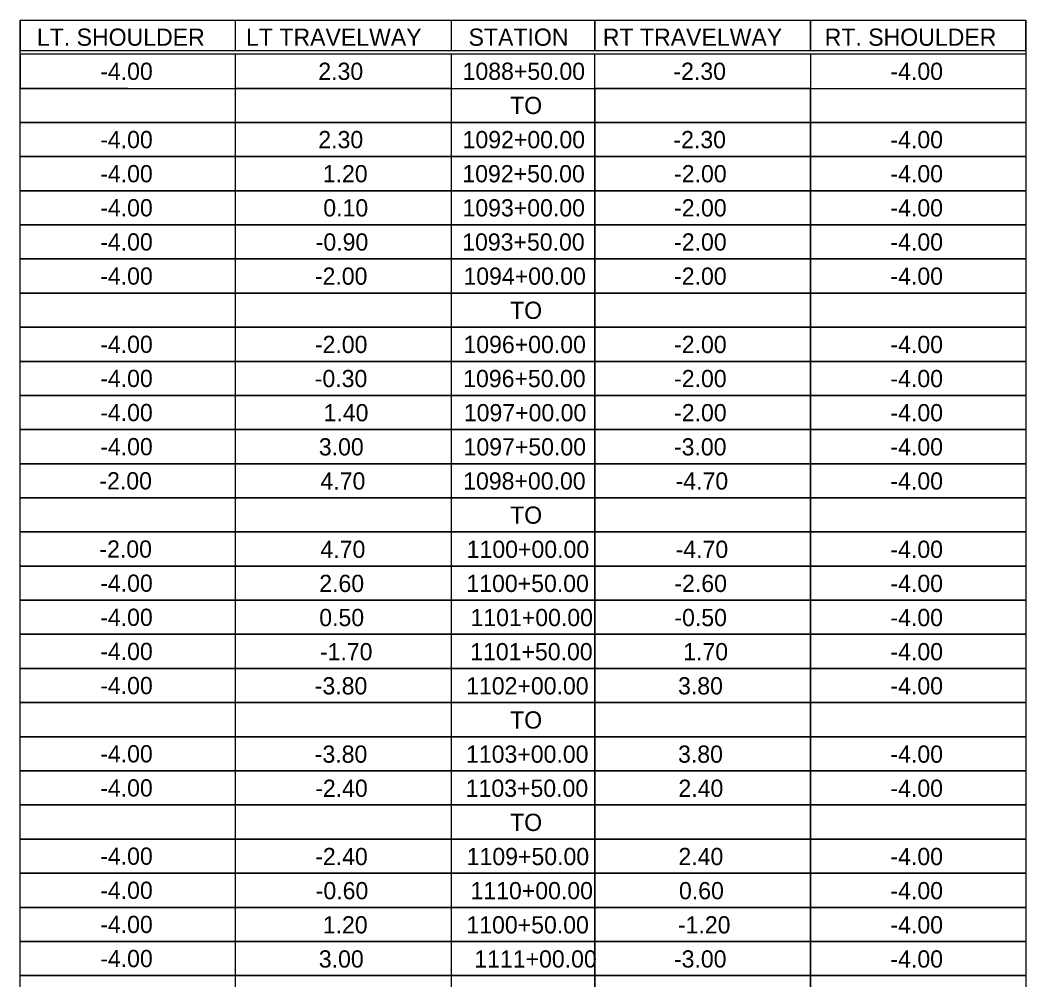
# Model space of a CAD drawing. Extents: x 1026502 to 1027102, y 781811 to 782040.
# Drawn here: x 1027074.42 to 1027102.42, y 781893.51 to 781920.24 of the extents above; entities that cross this region are included whole.
import ezdxf

# ---------------------------------------------------------------- set-up
doc = ezdxf.new("R2010")
doc.units = 0
for name, color, linetype in [('ANNOTATION', 7, 'Continuous'), ('BORDER', 7, 'Continuous'), ('DIMENSIONS', 7, 'Continuous')]:
    doc.layers.add(name, color=color, linetype=linetype)

msp = doc.modelspace()

# ---------------------------------------------------------------- linework, layer by layer
at = {"layer": 'ANNOTATION'}
msp.add_lwpolyline([(1027074.415, 781920.244), (1027102.415, 781920.244), (1027102.415, 781866.071), (1027074.415, 781866.071)], close=True, dxfattribs=at)
at = {"layer": 'BORDER'}
for p, q in [((1027074.415, 781920.244), (1027074.415, 781919.399)), ((1027077.415, 781919.293), (1027074.415, 781919.293)), ((1027074.415, 781919.293), (1027074.415, 781918.343)), ((1027102.415, 781919.293), (1027102.415, 781918.343)), ((1027077.415, 781918.343), (1027074.415, 781918.343)), ((1027077.415, 781918.343), (1027074.415, 781918.343)), ((1027077.415, 781917.393), (1027074.415, 781917.393)), ((1027077.415, 781917.393), (1027074.415, 781917.393)), ((1027077.415, 781917.393), (1027080.415, 781917.393)), ((1027077.415, 781916.442), (1027074.415, 781916.442)), ((1027077.415, 781916.442), (1027074.415, 781916.442)), ((1027077.415, 781916.442), (1027080.415, 781916.442)), ((1027077.415, 781915.492), (1027074.415, 781915.492)), ((1027077.415, 781915.492), (1027074.415, 781915.492)), ((1027077.415, 781915.492), (1027080.415, 781915.492)), ((1027077.415, 781914.541), (1027074.415, 781914.541)), ((1027077.415, 781914.541), (1027074.415, 781914.541)), ((1027077.415, 781914.541), (1027080.415, 781914.541)), ((1027077.415, 781913.591), (1027074.415, 781913.591)), ((1027077.415, 781913.591), (1027074.415, 781913.591)), ((1027077.415, 781913.591), (1027080.415, 781913.591)), ((1027077.415, 781912.641), (1027074.415, 781912.641)), ((1027077.415, 781912.641), (1027074.415, 781912.641)), ((1027077.415, 781912.641), (1027080.415, 781912.641)), ((1027077.415, 781911.69), (1027074.415, 781911.69)), ((1027077.415, 781911.69), (1027074.415, 781911.69)), ((1027077.415, 781911.69), (1027080.415, 781911.69)), ((1027077.415, 781910.74), (1027074.415, 781910.74)), ((1027077.415, 781910.74), (1027074.415, 781910.74)), ((1027077.415, 781910.74), (1027080.415, 781910.74)), ((1027077.415, 781909.789), (1027074.415, 781909.789)), ((1027077.415, 781909.789), (1027074.415, 781909.789)), ((1027077.415, 781909.789), (1027080.415, 781909.789)), ((1027077.415, 781908.839), (1027074.415, 781908.839)), ((1027077.415, 781908.839), (1027074.415, 781908.839)), ((1027077.415, 781908.839), (1027080.415, 781908.839)), ((1027077.415, 781907.889), (1027074.415, 781907.889)), ((1027077.415, 781907.889), (1027074.415, 781907.889)), ((1027077.415, 781907.889), (1027080.415, 781907.889)), ((1027077.415, 781906.938), (1027074.415, 781906.938)), ((1027077.415, 781906.938), (1027074.415, 781906.938)), ((1027077.415, 781906.938), (1027080.415, 781906.938)), ((1027077.415, 781905.988), (1027074.415, 781905.988)), ((1027077.415, 781905.988), (1027074.415, 781905.988)), ((1027077.415, 781905.988), (1027080.415, 781905.988)), ((1027077.415, 781905.037), (1027074.415, 781905.037)), ((1027077.415, 781905.037), (1027074.415, 781905.037)), ((1027077.415, 781905.037), (1027080.415, 781905.037)), ((1027077.415, 781904.087), (1027074.415, 781904.087)), ((1027077.415, 781904.087), (1027074.415, 781904.087)), ((1027077.415, 781904.087), (1027080.415, 781904.087)), ((1027077.415, 781903.137), (1027074.415, 781903.137)), ((1027077.415, 781903.137), (1027074.415, 781903.137)), ((1027077.415, 781903.137), (1027080.415, 781903.137)), ((1027077.415, 781902.186), (1027074.415, 781902.186)), ((1027077.415, 781902.186), (1027074.415, 781902.186)), ((1027077.415, 781902.186), (1027080.415, 781902.186)), ((1027077.415, 781901.236), (1027074.415, 781901.236)), ((1027077.415, 781901.236), (1027074.415, 781901.236)), ((1027077.415, 781901.236), (1027080.415, 781901.236)), ((1027077.415, 781900.285), (1027074.415, 781900.285)), ((1027077.415, 781900.285), (1027074.415, 781900.285)), ((1027077.415, 781900.285), (1027080.415, 781900.285)), ((1027077.415, 781899.335), (1027074.415, 781899.335)), ((1027077.415, 781899.335), (1027074.415, 781899.335)), ((1027077.415, 781899.335), (1027080.415, 781899.335)), ((1027077.415, 781898.385), (1027074.415, 781898.385)), ((1027077.415, 781898.385), (1027074.415, 781898.385)), ((1027077.415, 781898.385), (1027080.415, 781898.385)), ((1027077.415, 781897.434), (1027074.415, 781897.434)), ((1027077.415, 781897.434), (1027074.415, 781897.434)), ((1027077.415, 781897.434), (1027080.415, 781897.434)), ((1027077.415, 781896.484), (1027074.415, 781896.484)), ((1027077.415, 781896.484), (1027074.415, 781896.484)), ((1027077.415, 781896.484), (1027080.415, 781896.484)), ((1027077.415, 781895.533), (1027074.415, 781895.533)), ((1027077.415, 781895.533), (1027074.415, 781895.533)), ((1027077.415, 781895.533), (1027080.415, 781895.533)), ((1027077.415, 781894.583), (1027074.415, 781894.583)), ((1027077.415, 781894.583), (1027074.415, 781894.583)), ((1027077.415, 781894.583), (1027080.415, 781894.583)), ((1027077.415, 781893.633), (1027074.415, 781893.633)), ((1027077.415, 781893.633), (1027074.415, 781893.633)), ((1027077.415, 781893.633), (1027080.415, 781893.633))]:
    msp.add_line(p, q, dxfattribs=at)
for points in [[(1027074.415, 781920.244), (1027102.415, 781920.244), (1027102.415, 781919.293), (1027074.415, 781919.293)], [(1027074.415, 781918.343), (1027102.415, 781918.343), (1027102.415, 781917.393), (1027074.415, 781917.393)], [(1027074.415, 781917.393), (1027102.415, 781917.393), (1027102.415, 781916.442), (1027074.415, 781916.442)], [(1027074.415, 781916.442), (1027102.415, 781916.442), (1027102.415, 781915.492), (1027074.415, 781915.492)], [(1027074.415, 781915.492), (1027102.415, 781915.492), (1027102.415, 781914.541), (1027074.415, 781914.541)], [(1027074.415, 781914.541), (1027102.415, 781914.541), (1027102.415, 781913.591), (1027074.415, 781913.591)], [(1027074.415, 781913.591), (1027102.415, 781913.591), (1027102.415, 781912.641), (1027074.415, 781912.641)], [(1027074.415, 781912.641), (1027102.415, 781912.641), (1027102.415, 781911.69), (1027074.415, 781911.69)], [(1027074.415, 781911.69), (1027102.415, 781911.69), (1027102.415, 781910.74), (1027074.415, 781910.74)], [(1027074.415, 781910.74), (1027102.415, 781910.74), (1027102.415, 781909.789), (1027074.415, 781909.789)], [(1027074.415, 781909.789), (1027102.415, 781909.789), (1027102.415, 781908.839), (1027074.415, 781908.839)], [(1027074.415, 781908.839), (1027102.415, 781908.839), (1027102.415, 781907.889), (1027074.415, 781907.889)], [(1027074.415, 781907.889), (1027102.415, 781907.889), (1027102.415, 781906.938), (1027074.415, 781906.938)], [(1027074.415, 781906.938), (1027102.415, 781906.938), (1027102.415, 781905.988), (1027074.415, 781905.988)], [(1027074.415, 781905.988), (1027102.415, 781905.988), (1027102.415, 781905.037), (1027074.415, 781905.037)], [(1027074.415, 781905.037), (1027102.415, 781905.037), (1027102.415, 781904.087), (1027074.415, 781904.087)], [(1027074.415, 781904.087), (1027102.415, 781904.087), (1027102.415, 781903.137), (1027074.415, 781903.137)], [(1027074.415, 781903.137), (1027102.415, 781903.137), (1027102.415, 781902.186), (1027074.415, 781902.186)], [(1027074.415, 781902.186), (1027102.415, 781902.186), (1027102.415, 781901.236), (1027074.415, 781901.236)], [(1027074.415, 781901.236), (1027102.415, 781901.236), (1027102.415, 781900.285), (1027074.415, 781900.285)], [(1027074.415, 781900.285), (1027102.415, 781900.285), (1027102.415, 781899.335), (1027074.415, 781899.335)], [(1027074.415, 781899.335), (1027102.415, 781899.335), (1027102.415, 781898.385), (1027074.415, 781898.385)], [(1027074.415, 781898.385), (1027102.415, 781898.385), (1027102.415, 781897.434), (1027074.415, 781897.434)], [(1027074.415, 781897.434), (1027102.415, 781897.434), (1027102.415, 781896.484), (1027074.415, 781896.484)], [(1027074.415, 781896.484), (1027102.415, 781896.484), (1027102.415, 781895.533), (1027074.415, 781895.533)], [(1027074.415, 781895.533), (1027102.415, 781895.533), (1027102.415, 781894.583), (1027074.415, 781894.583)], [(1027074.415, 781894.583), (1027102.415, 781894.583), (1027102.415, 781893.633), (1027074.415, 781893.633)], [(1027074.415, 781893.633), (1027102.415, 781893.633), (1027102.415, 781892.682), (1027074.415, 781892.682)]]:
    msp.add_lwpolyline(points, close=True, dxfattribs=at)
for points in [[(1027074.415, 781919.399), (1027102.415, 781919.399), (1027102.415, 781920.244)], [(1027080.415, 781919.399), (1027080.415, 781920.244)], [(1027086.415, 781920.244), (1027086.415, 781919.399)], [(1027090.415, 781920.244), (1027090.415, 781919.399)], [(1027090.415, 781919.399), (1027090.415, 781920.244)], [(1027096.415, 781920.244), (1027096.415, 781919.399)], [(1027096.415, 781919.399), (1027096.415, 781920.244)], [(1027102.415, 781920.244), (1027102.415, 781919.399)], [(1027086.415, 781919.293), (1027086.415, 781918.343), (1027080.415, 781918.343), (1027080.415, 781919.293)], [(1027096.415, 781919.293), (1027096.415, 781918.343), (1027090.415, 781918.343), (1027090.415, 781919.293)], [(1027086.415, 781918.343), (1027086.415, 781917.393), (1027080.415, 781917.393), (1027080.415, 781918.343)], [(1027090.415, 781918.343), (1027090.415, 781917.393), (1027086.415, 781917.393)], [(1027096.415, 781918.343), (1027096.415, 781917.393), (1027090.415, 781917.393), (1027090.415, 781918.343)], [(1027102.415, 781918.343), (1027102.415, 781917.393), (1027096.415, 781917.393), (1027096.415, 781918.343)], [(1027086.415, 781917.393), (1027086.415, 781916.442), (1027080.415, 781916.442), (1027080.415, 781917.393)], [(1027090.415, 781917.393), (1027090.415, 781916.442), (1027086.415, 781916.442)], [(1027096.415, 781917.393), (1027096.415, 781916.442), (1027090.415, 781916.442), (1027090.415, 781917.393)], [(1027102.415, 781917.393), (1027102.415, 781916.442), (1027096.415, 781916.442), (1027096.415, 781917.393)], [(1027086.415, 781916.442), (1027086.415, 781915.492), (1027080.415, 781915.492), (1027080.415, 781916.442)], [(1027090.415, 781916.442), (1027090.415, 781915.492), (1027086.415, 781915.492)], [(1027096.415, 781916.442), (1027096.415, 781915.492), (1027090.415, 781915.492), (1027090.415, 781916.442)], [(1027102.415, 781916.442), (1027102.415, 781915.492), (1027096.415, 781915.492), (1027096.415, 781916.442)], [(1027086.415, 781915.492), (1027086.415, 781914.541), (1027080.415, 781914.541), (1027080.415, 781915.492)], [(1027090.415, 781915.492), (1027090.415, 781914.541), (1027086.415, 781914.541)], [(1027096.415, 781915.492), (1027096.415, 781914.541), (1027090.415, 781914.541), (1027090.415, 781915.492)], [(1027102.415, 781915.492), (1027102.415, 781914.541), (1027096.415, 781914.541), (1027096.415, 781915.492)], [(1027086.415, 781914.541), (1027086.415, 781913.591), (1027080.415, 781913.591), (1027080.415, 781914.541)], [(1027090.415, 781914.541), (1027090.415, 781913.591), (1027086.415, 781913.591)], [(1027096.415, 781914.541), (1027096.415, 781913.591), (1027090.415, 781913.591), (1027090.415, 781914.541)], [(1027102.415, 781914.541), (1027102.415, 781913.591), (1027096.415, 781913.591), (1027096.415, 781914.541)], [(1027086.415, 781913.591), (1027086.415, 781912.641), (1027080.415, 781912.641), (1027080.415, 781913.591)], [(1027090.415, 781913.591), (1027090.415, 781912.641), (1027086.415, 781912.641)], [(1027096.415, 781913.591), (1027096.415, 781912.641), (1027090.415, 781912.641), (1027090.415, 781913.591)], [(1027102.415, 781913.591), (1027102.415, 781912.641), (1027096.415, 781912.641), (1027096.415, 781913.591)], [(1027086.415, 781912.641), (1027086.415, 781911.69), (1027080.415, 781911.69), (1027080.415, 781912.641)], [(1027090.415, 781912.641), (1027090.415, 781911.69), (1027086.415, 781911.69)], [(1027096.415, 781912.641), (1027096.415, 781911.69), (1027090.415, 781911.69), (1027090.415, 781912.641)], [(1027102.415, 781912.641), (1027102.415, 781911.69), (1027096.415, 781911.69), (1027096.415, 781912.641)], [(1027086.415, 781911.69), (1027086.415, 781910.74), (1027080.415, 781910.74), (1027080.415, 781911.69)], [(1027090.415, 781911.69), (1027090.415, 781910.74), (1027086.415, 781910.74)], [(1027096.415, 781911.69), (1027096.415, 781910.74), (1027090.415, 781910.74), (1027090.415, 781911.69)], [(1027102.415, 781911.69), (1027102.415, 781910.74), (1027096.415, 781910.74), (1027096.415, 781911.69)], [(1027086.415, 781910.74), (1027086.415, 781909.789), (1027080.415, 781909.789), (1027080.415, 781910.74)], [(1027090.415, 781910.74), (1027090.415, 781909.789), (1027086.415, 781909.789)], [(1027096.415, 781910.74), (1027096.415, 781909.789), (1027090.415, 781909.789), (1027090.415, 781910.74)], [(1027102.415, 781910.74), (1027102.415, 781909.789), (1027096.415, 781909.789), (1027096.415, 781910.74)], [(1027086.415, 781909.789), (1027086.415, 781908.839), (1027080.415, 781908.839), (1027080.415, 781909.789)], [(1027090.415, 781909.789), (1027090.415, 781908.839), (1027086.415, 781908.839)], [(1027096.415, 781909.789), (1027096.415, 781908.839), (1027090.415, 781908.839), (1027090.415, 781909.789)], [(1027102.415, 781909.789), (1027102.415, 781908.839), (1027096.415, 781908.839), (1027096.415, 781909.789)], [(1027086.415, 781908.839), (1027086.415, 781907.889), (1027080.415, 781907.889), (1027080.415, 781908.839)], [(1027090.415, 781908.839), (1027090.415, 781907.889), (1027086.415, 781907.889)], [(1027096.415, 781908.839), (1027096.415, 781907.889), (1027090.415, 781907.889), (1027090.415, 781908.839)], [(1027102.415, 781908.839), (1027102.415, 781907.889), (1027096.415, 781907.889), (1027096.415, 781908.839)], [(1027086.415, 781907.889), (1027086.415, 781906.938), (1027080.415, 781906.938), (1027080.415, 781907.889)], [(1027090.415, 781907.889), (1027090.415, 781906.938), (1027086.415, 781906.938)], [(1027096.415, 781907.889), (1027096.415, 781906.938), (1027090.415, 781906.938), (1027090.415, 781907.889)], [(1027102.415, 781907.889), (1027102.415, 781906.938), (1027096.415, 781906.938), (1027096.415, 781907.889)], [(1027086.415, 781906.938), (1027086.415, 781905.988), (1027080.415, 781905.988), (1027080.415, 781906.938)], [(1027090.415, 781906.938), (1027090.415, 781905.988), (1027086.415, 781905.988)], [(1027096.415, 781906.938), (1027096.415, 781905.988), (1027090.415, 781905.988), (1027090.415, 781906.938)], [(1027102.415, 781906.938), (1027102.415, 781905.988), (1027096.415, 781905.988), (1027096.415, 781906.938)], [(1027086.415, 781905.988), (1027086.415, 781905.037), (1027080.415, 781905.037), (1027080.415, 781905.988)], [(1027090.415, 781905.988), (1027090.415, 781905.037), (1027086.415, 781905.037)], [(1027096.415, 781905.988), (1027096.415, 781905.037), (1027090.415, 781905.037), (1027090.415, 781905.988)], [(1027102.415, 781905.988), (1027102.415, 781905.037), (1027096.415, 781905.037), (1027096.415, 781905.988)], [(1027086.415, 781905.037), (1027086.415, 781904.087), (1027080.415, 781904.087), (1027080.415, 781905.037)], [(1027090.415, 781905.037), (1027090.415, 781904.087), (1027086.415, 781904.087)], [(1027096.415, 781905.037), (1027096.415, 781904.087), (1027090.415, 781904.087), (1027090.415, 781905.037)], [(1027102.415, 781905.037), (1027102.415, 781904.087), (1027096.415, 781904.087), (1027096.415, 781905.037)], [(1027086.415, 781904.087), (1027086.415, 781903.137), (1027080.415, 781903.137), (1027080.415, 781904.087)], [(1027090.415, 781904.087), (1027090.415, 781903.137), (1027086.415, 781903.137)], [(1027096.415, 781904.087), (1027096.415, 781903.137), (1027090.415, 781903.137), (1027090.415, 781904.087)], [(1027102.415, 781904.087), (1027102.415, 781903.137), (1027096.415, 781903.137), (1027096.415, 781904.087)], [(1027086.415, 781903.137), (1027086.415, 781902.186), (1027080.415, 781902.186), (1027080.415, 781903.137)], [(1027090.415, 781903.137), (1027090.415, 781902.186), (1027086.415, 781902.186)], [(1027096.415, 781903.137), (1027096.415, 781902.186), (1027090.415, 781902.186), (1027090.415, 781903.137)], [(1027102.415, 781903.137), (1027102.415, 781902.186), (1027096.415, 781902.186), (1027096.415, 781903.137)], [(1027086.415, 781902.186), (1027086.415, 781901.236), (1027080.415, 781901.236), (1027080.415, 781902.186)], [(1027090.415, 781902.186), (1027090.415, 781901.236), (1027086.415, 781901.236)], [(1027096.415, 781902.186), (1027096.415, 781901.236), (1027090.415, 781901.236), (1027090.415, 781902.186)], [(1027102.415, 781902.186), (1027102.415, 781901.236), (1027096.415, 781901.236), (1027096.415, 781902.186)], [(1027086.415, 781901.236), (1027086.415, 781900.285), (1027080.415, 781900.285), (1027080.415, 781901.236)], [(1027090.415, 781901.236), (1027090.415, 781900.285), (1027086.415, 781900.285)], [(1027096.415, 781901.236), (1027096.415, 781900.285), (1027090.415, 781900.285), (1027090.415, 781901.236)], [(1027102.415, 781901.236), (1027102.415, 781900.285), (1027096.415, 781900.285), (1027096.415, 781901.236)], [(1027086.415, 781900.285), (1027086.415, 781899.335), (1027080.415, 781899.335), (1027080.415, 781900.285)], [(1027090.415, 781900.285), (1027090.415, 781899.335), (1027086.415, 781899.335)], [(1027096.415, 781900.285), (1027096.415, 781899.335), (1027090.415, 781899.335), (1027090.415, 781900.285)], [(1027102.415, 781900.285), (1027102.415, 781899.335), (1027096.415, 781899.335), (1027096.415, 781900.285)], [(1027086.415, 781899.335), (1027086.415, 781898.385), (1027080.415, 781898.385), (1027080.415, 781899.335)], [(1027090.415, 781899.335), (1027090.415, 781898.385), (1027086.415, 781898.385)], [(1027096.415, 781899.335), (1027096.415, 781898.385), (1027090.415, 781898.385), (1027090.415, 781899.335)], [(1027102.415, 781899.335), (1027102.415, 781898.385), (1027096.415, 781898.385), (1027096.415, 781899.335)], [(1027086.415, 781898.385), (1027086.415, 781897.434), (1027080.415, 781897.434), (1027080.415, 781898.385)], [(1027090.415, 781898.385), (1027090.415, 781897.434), (1027086.415, 781897.434)], [(1027096.415, 781898.385), (1027096.415, 781897.434), (1027090.415, 781897.434), (1027090.415, 781898.385)], [(1027102.415, 781898.385), (1027102.415, 781897.434), (1027096.415, 781897.434), (1027096.415, 781898.385)], [(1027086.415, 781897.434), (1027086.415, 781896.484), (1027080.415, 781896.484), (1027080.415, 781897.434)], [(1027090.415, 781897.434), (1027090.415, 781896.484), (1027086.415, 781896.484)], [(1027096.415, 781897.434), (1027096.415, 781896.484), (1027090.415, 781896.484), (1027090.415, 781897.434)], [(1027102.415, 781897.434), (1027102.415, 781896.484), (1027096.415, 781896.484), (1027096.415, 781897.434)], [(1027086.415, 781896.484), (1027086.415, 781895.533), (1027080.415, 781895.533), (1027080.415, 781896.484)], [(1027090.415, 781896.484), (1027090.415, 781895.533), (1027086.415, 781895.533)], [(1027096.415, 781896.484), (1027096.415, 781895.533), (1027090.415, 781895.533), (1027090.415, 781896.484)], [(1027102.415, 781896.484), (1027102.415, 781895.533), (1027096.415, 781895.533), (1027096.415, 781896.484)], [(1027086.415, 781895.533), (1027086.415, 781894.583), (1027080.415, 781894.583), (1027080.415, 781895.533)], [(1027090.415, 781895.533), (1027090.415, 781894.583), (1027086.415, 781894.583)], [(1027096.415, 781895.533), (1027096.415, 781894.583), (1027090.415, 781894.583), (1027090.415, 781895.533)], [(1027102.415, 781895.533), (1027102.415, 781894.583), (1027096.415, 781894.583), (1027096.415, 781895.533)], [(1027086.415, 781894.583), (1027086.415, 781893.633), (1027080.415, 781893.633), (1027080.415, 781894.583)], [(1027090.415, 781894.583), (1027090.415, 781893.633), (1027086.415, 781893.633)], [(1027096.415, 781894.583), (1027096.415, 781893.633), (1027090.415, 781893.633), (1027090.415, 781894.583)], [(1027102.415, 781894.583), (1027102.415, 781893.633), (1027096.415, 781893.633), (1027096.415, 781894.583)], [(1027086.415, 781893.633), (1027086.415, 781892.682), (1027080.415, 781892.682), (1027080.415, 781893.633)], [(1027090.415, 781893.633), (1027090.415, 781892.682), (1027086.415, 781892.682)], [(1027096.415, 781893.633), (1027096.415, 781892.682), (1027090.415, 781892.682), (1027090.415, 781893.633)], [(1027102.415, 781893.633), (1027102.415, 781892.682), (1027096.415, 781892.682), (1027096.415, 781893.633)]]:
    msp.add_lwpolyline(points, dxfattribs=at)

# ---------------------------------------------------------------- texts
at = {"layer": 'DIMENSIONS'}
for s, p in [('LT. SHOULDER', (1027074.883, 781919.529)), ('LT TRAVELWAY', (1027080.706, 781919.529)), ('STATION', (1027086.9, 781919.529)), ('RT TRAVELWAY', (1027090.638, 781919.529)), ('RT. SHOULDER', (1027096.814, 781919.529)), ('-4.00', (1027076.645, 781918.578)), ('2.30', (1027082.717, 781918.578)), ('1088+50.00', (1027086.734, 781918.578)), ('-2.30', (1027092.603, 781918.578)), ('-4.00', (1027098.645, 781918.578)), ('TO', (1027088.057, 781917.627)), ('-4.00', (1027076.645, 781916.677)), ('2.30', (1027082.717, 781916.676)), ('1092+00.00', (1027086.734, 781916.676)), ('-2.30', (1027092.603, 781916.676)), ('-4.00', (1027098.645, 781916.676)), ('-4.00', (1027076.645, 781915.727)), ('1.20', (1027082.841, 781915.726)), ('1092+50.00', (1027086.727, 781915.726)), ('-2.00', (1027092.622, 781915.726)), ('-4.00', (1027098.645, 781915.726)), ('-4.00', (1027076.645, 781914.777)), ('0.10', (1027082.856, 781914.775)), ('1093+00.00', (1027086.731, 781914.775)), ('-2.00', (1027092.622, 781914.775)), ('-4.00', (1027098.645, 781914.775)), ('-4.00', (1027076.645, 781913.826)), ('-0.90', (1027082.645, 781913.824)), ('1093+50.00', (1027086.723, 781913.824)), ('-2.00', (1027092.622, 781913.824)), ('-4.00', (1027098.645, 781913.824)), ('-4.00', (1027076.645, 781912.876)), ('-2.00', (1027082.622, 781912.873)), ('1094+00.00', (1027086.757, 781912.873)), ('-2.00', (1027092.622, 781912.873)), ('-4.00', (1027098.645, 781912.873)), ('TO', (1027088.057, 781911.922)), ('-4.00', (1027076.645, 781910.975)), ('-2.00', (1027082.622, 781910.971)), ('1096+00.00', (1027086.757, 781910.971)), ('-2.00', (1027092.622, 781910.971)), ('-4.00', (1027098.645, 781910.971)), ('-4.00', (1027076.645, 781910.025)), ('-0.30', (1027082.618, 781910.021)), ('1096+50.00', (1027086.75, 781910.021)), ('-2.00', (1027092.622, 781910.021)), ('-4.00', (1027098.645, 781910.021)), ('-4.00', (1027076.645, 781909.074)), ('1.40', (1027082.864, 781909.07)), ('1097+00.00', (1027086.768, 781909.07)), ('-2.00', (1027092.622, 781909.07)), ('-4.00', (1027098.645, 781909.07)), ('-4.00', (1027076.645, 781908.124)), ('3.00', (1027082.732, 781908.119)), ('1097+50.00', (1027086.761, 781908.119)), ('-3.00', (1027092.618, 781908.119)), ('-4.00', (1027098.645, 781908.119)), ('-2.00', (1027076.622, 781907.173)), ('4.70', (1027082.777, 781907.168)), ('1098+00.00', (1027086.75, 781907.168)), ('-4.70', (1027092.664, 781907.168)), ('-4.00', (1027098.645, 781907.168)), ('TO', (1027088.057, 781906.217)), ('-2.00', (1027076.622, 781905.273)), ('4.70', (1027082.777, 781905.266)), ('1100+00.00', (1027086.848, 781905.266)), ('-4.70', (1027092.664, 781905.266)), ('-4.00', (1027098.645, 781905.266)), ('-4.00', (1027076.645, 781904.322)), ('2.60', (1027082.743, 781904.316)), ('1100+50.00', (1027086.84, 781904.316)), ('-2.60', (1027092.63, 781904.316)), ('-4.00', (1027098.645, 781904.316)), ('-4.00', (1027076.645, 781903.372)), ('0.50', (1027082.743, 781903.365)), ('1101+00.00', (1027086.954, 781903.365)), ('-0.50', (1027092.63, 781903.365)), ('-4.00', (1027098.645, 781903.365)), ('-4.00', (1027076.645, 781902.421)), ('-1.70', (1027082.762, 781902.414)), ('1101+50.00', (1027086.946, 781902.414)), ('1.70', (1027092.875, 781902.414)), ('-4.00', (1027098.645, 781902.414)), ('-4.00', (1027076.645, 781901.471)), ('-3.80', (1027082.618, 781901.463)), ('1102+00.00', (1027086.833, 781901.463)), ('3.80', (1027092.732, 781901.463)), ('-4.00', (1027098.645, 781901.463)), ('TO', (1027088.057, 781900.512)), ('-4.00', (1027076.645, 781899.57)), ('-3.80', (1027082.618, 781899.561)), ('1103+00.00', (1027086.829, 781899.561)), ('3.80', (1027092.732, 781899.561)), ('-4.00', (1027098.645, 781899.561)), ('-4.00', (1027076.645, 781898.62)), ('-2.40', (1027082.63, 781898.611)), ('1103+50.00', (1027086.821, 781898.611)), ('2.40', (1027092.743, 781898.611)), ('-4.00', (1027098.645, 781898.611)), ('TO', (1027088.057, 781897.66)), ('-4.00', (1027076.645, 781896.719)), ('-2.40', (1027082.63, 781896.709)), ('1109+50.00', (1027086.848, 781896.709)), ('2.40', (1027092.743, 781896.709)), ('-4.00', (1027098.645, 781896.709)), ('-4.00', (1027076.645, 781895.769)), ('-0.60', (1027082.645, 781895.758)), ('1110+00.00', (1027086.954, 781895.758)), ('0.60', (1027092.758, 781895.758)), ('-4.00', (1027098.645, 781895.758)), ('-4.00', (1027076.645, 781894.818)), ('1.20', (1027082.841, 781894.807)), ('1100+50.00', (1027086.84, 781894.807)), ('-1.20', (1027092.728, 781894.807)), ('-4.00', (1027098.645, 781894.807)), ('-4.00', (1027076.645, 781893.868)), ('3.00', (1027082.732, 781893.856)), ('1111+00.00', (1027087.06, 781893.856)), ('-3.00', (1027092.618, 781893.856)), ('-4.00', (1027098.645, 781893.856))]:
    msp.add_text(s, height=0.48, dxfattribs=at).set_placement(p)

doc.saveas('drawing.dxf')
